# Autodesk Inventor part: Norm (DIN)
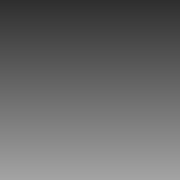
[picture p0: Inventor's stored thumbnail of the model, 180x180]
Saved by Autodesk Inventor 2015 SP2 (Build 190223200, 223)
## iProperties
Created: 2012-02
Part Number: Norm (DIN)
Material: Allgemein
Document SubType Name: Modeling
Designer: x86 deu
Density: 1 g/cm^3
Appearance: Vorgabe
Author: x86 deu
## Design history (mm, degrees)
